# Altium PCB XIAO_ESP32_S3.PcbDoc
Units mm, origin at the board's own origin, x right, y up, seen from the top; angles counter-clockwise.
Board outline 54 x 39 mm, 2 copper layers (Top Layer, Bottom Layer), stack 1.671 mm thick; 8 components, 14 nets, 41 pads, 0 vias.
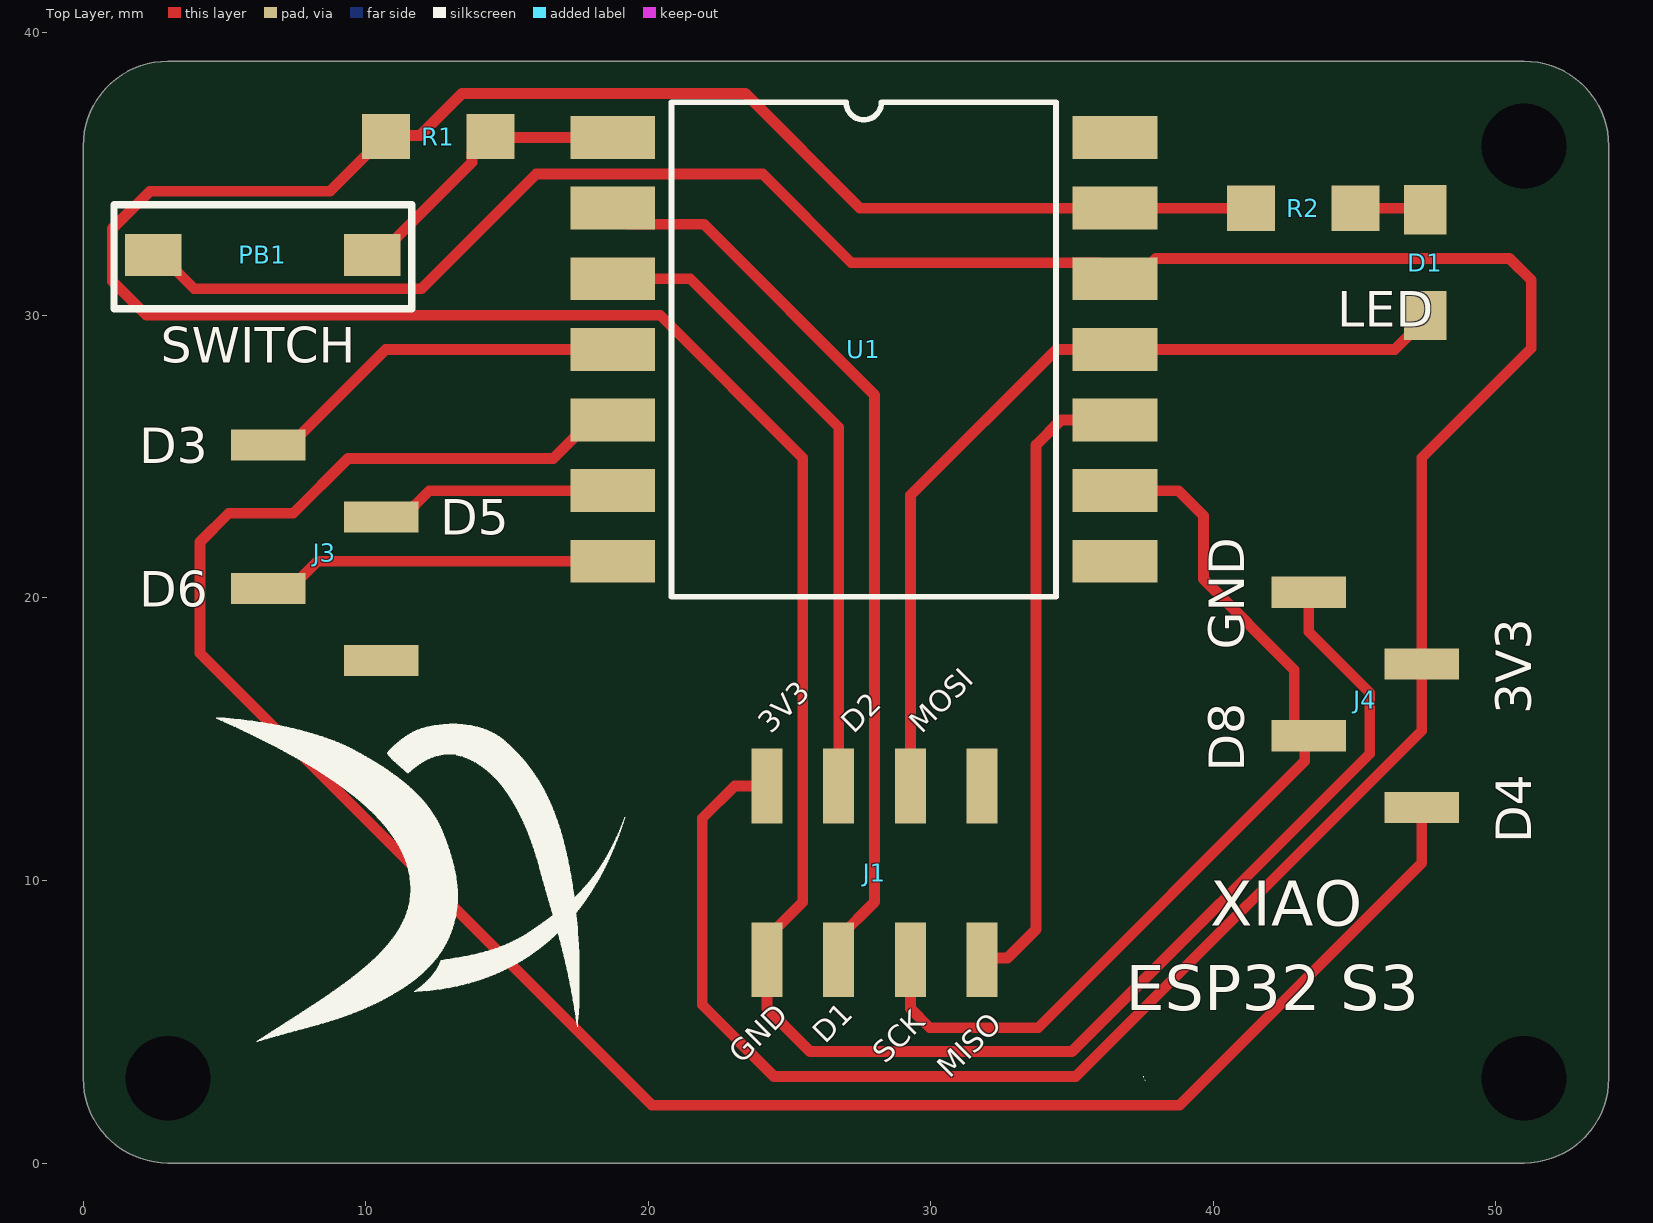
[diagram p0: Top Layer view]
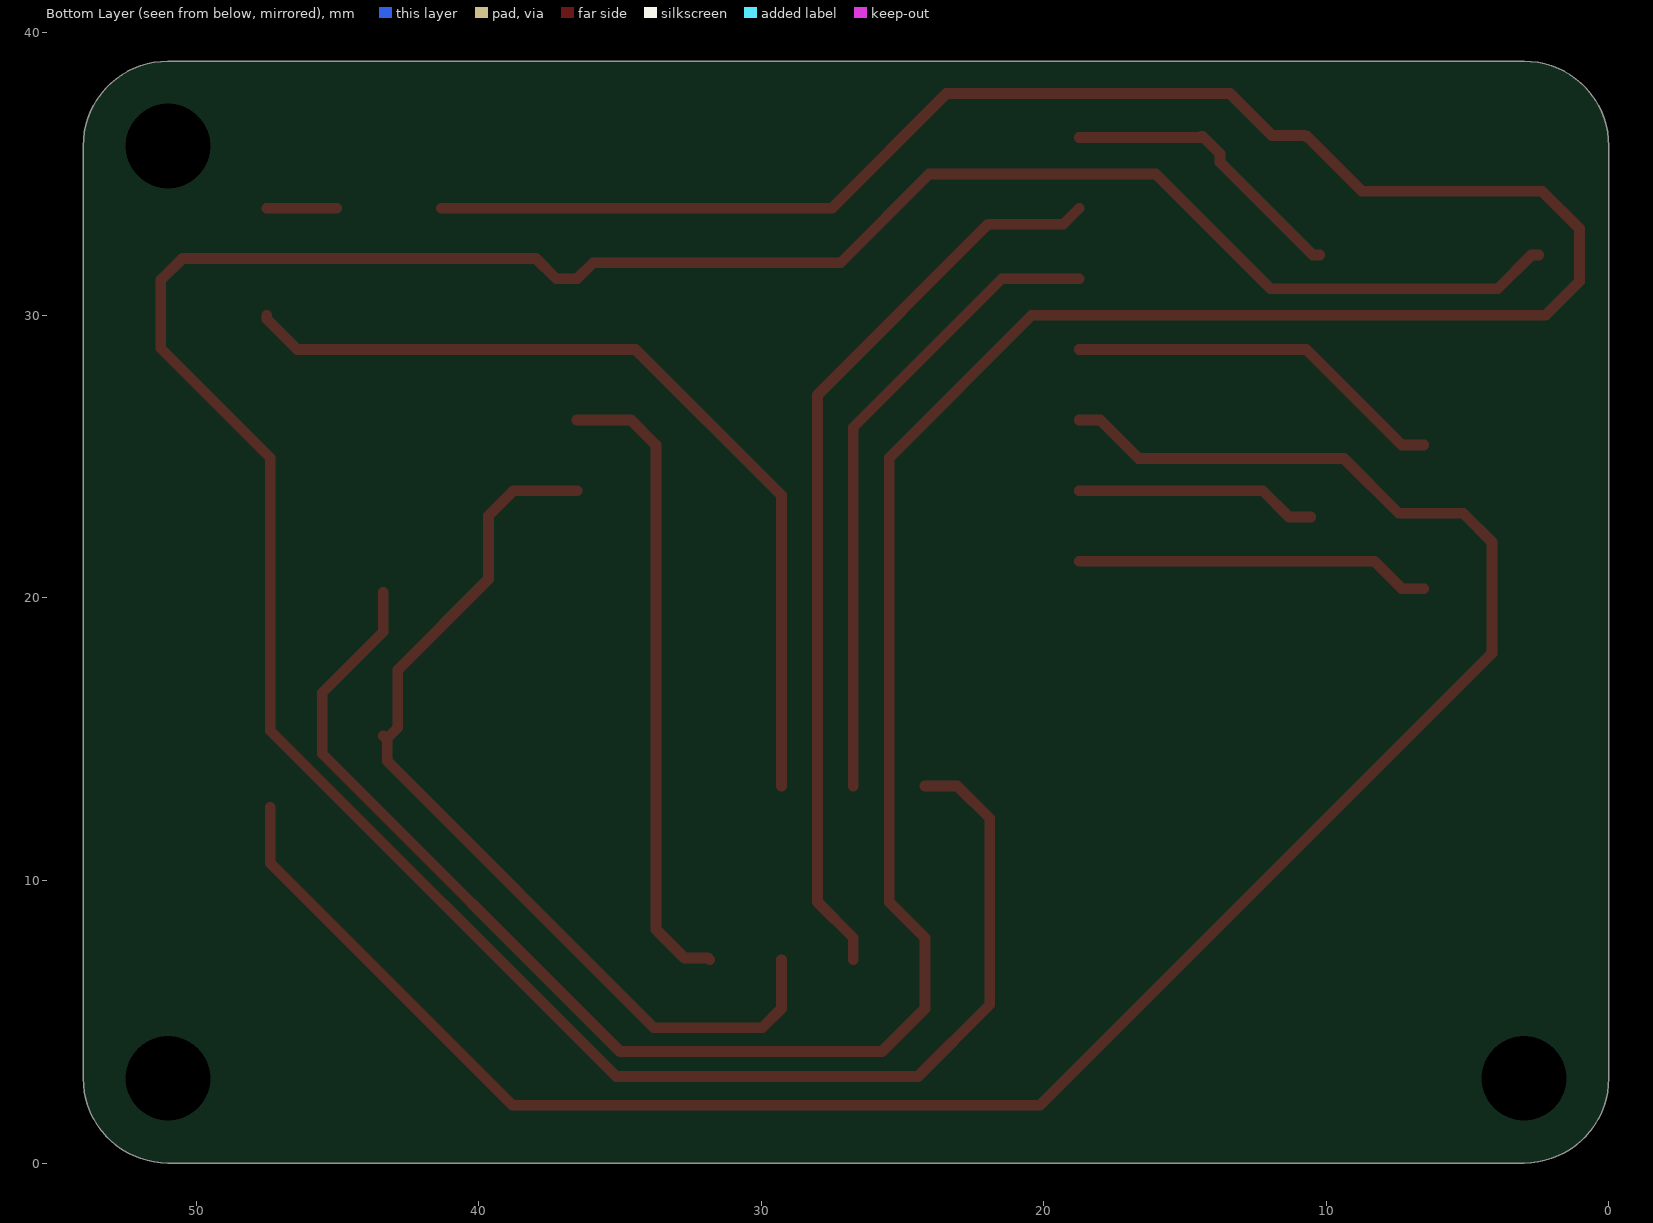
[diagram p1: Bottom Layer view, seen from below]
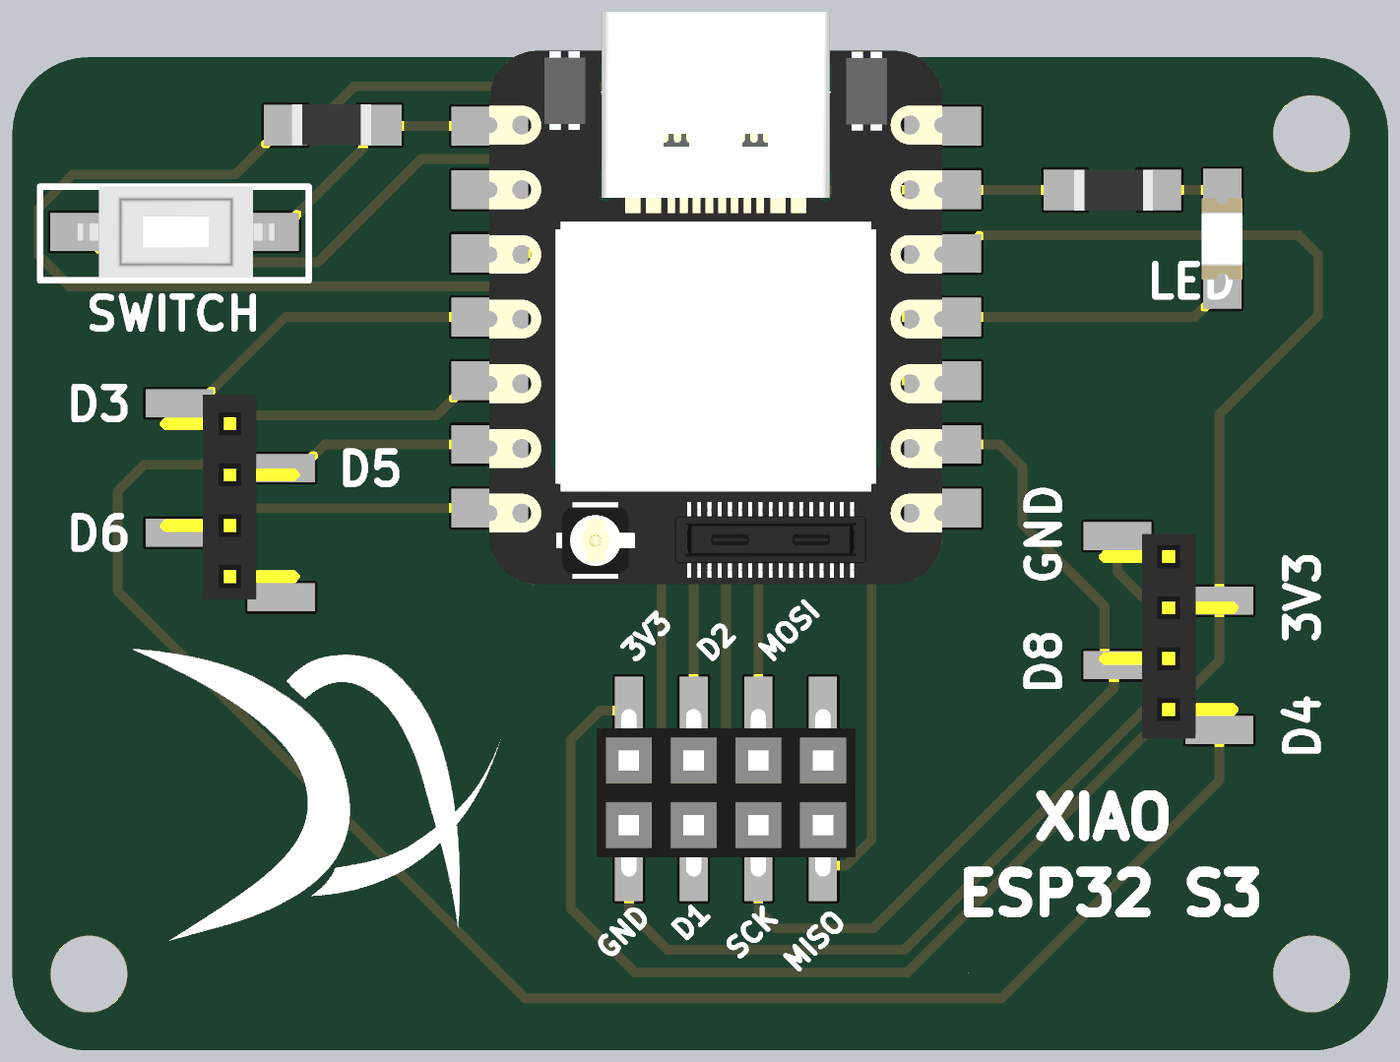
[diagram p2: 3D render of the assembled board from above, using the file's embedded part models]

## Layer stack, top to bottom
Top Solder: solder mask 0.0102, Solder Resist, Dk 3.5
Top Layer: signal copper 0.0356
Dielectric 1: dielectric 1.6, FR-4, Dk 4.8
Bottom Layer: signal copper 0.0356
Bottom Solder: solder mask 0.0102, Solder Resist, Dk 3.5

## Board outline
3,0 cw(c3,3) 0,3 0,36 cw(c3,36) 3,39 51,39 cw(c51,36) 54,36 54,3 cw(c51,3) 51,0

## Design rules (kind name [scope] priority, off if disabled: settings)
Clearance [All] p1: gap=0.254 ignorepadtopadclearanceinfootprint=FALSE
PolygonConnect [All] p1: connectstyle=Relief reliefconductorwidth=0.254 reliefentries=4 polygonreliefangle="90 Angle" airgapwidth=0.254
RoutingVias [All] p1: holewidth=0.711 width=1.27 viastyle="Through Hole" minholewidth=0.711 minwidth=1.27 maxholewidth=0.711 maxwidth=1.27
SolderMaskExpansion [All] p1: expansion=0.102 istentingtop=FALSE
SupplyNets "Schematic Supply Nets_2" [InNet('5V')] p1: voltage=0.000
SupplyNets "Schematic Supply Nets_1" [InNet('3V3')] p2: voltage=0.000
SupplyNets "Schematic Supply Nets" [InNet('GND')] p3: voltage=0.000
Width [All] p1: maxlimit=0.762 minlimit=0.254 preferedwidth=0.381 minimp=50.000000 maximp=50.000000 favimp=50.000000
30 further rules are at their usual default settings.

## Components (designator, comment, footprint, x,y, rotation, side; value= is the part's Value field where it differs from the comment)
D1 "Led" LED1206 47.5,33.75 r270 top
J1 "Header 4x2" HDR4X2_FEMALE 24.201,7.196 r90 top
J3 "Header 1x4" HDR4X1_FEMALE 6.548,25.411 r0 top
J4 "Header 1x4" HDR4X1_FEMALE 47.378,12.584 r180 top
PB1 "Push_button" "6x3x2.5mm SMD" 10.231,32.142 r180 top
R1 "R10K" RES1206 10.722,36.333 r0 top
R2 "R499" RES1206 45.029,33.793 r180 top
U1 "XIAO ESP32 S3" XIAO_ESP32_S3 18.74,36.3 r0 top

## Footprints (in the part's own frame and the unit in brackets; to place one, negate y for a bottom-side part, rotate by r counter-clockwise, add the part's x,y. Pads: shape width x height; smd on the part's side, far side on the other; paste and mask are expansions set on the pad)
"6x3x2.5mm SMD" [mm]
  rect 2x1.5 smd: 1(0,0) 2(7.75,0)
  silkscreen extent -1.4,-1.78 9.14,1.91, body extent -0.08,-1.79 7.7,1.79, height 2.54
HDR4X1_FEMALE [mm]
  rect 2.65x1.1 smd: 1(0,0) 2(4,-2.54) 3(0,-5.08) 4(4,-7.62)
  body extent -0.76,-7.7 4.74,0.34, height 2.33
HDR4X2_FEMALE [mm]
  rect 2.65x1.1 smd: 1(0,0) 2(0,-2.54) 3(0,-5.08) 4(0,-7.62) 5(6.15,-7.62) 6(6.15,-5.08) 7(6.15,-2.54) 8(6.15,0)
  body extent -0.37,-8.89 6.21,1.27, height 7.5
LED1206 [mm]
  rect 1.75x1.5 smd: 1(0,0) 2(3.75,0)
  body extent 0.28,-0.81 3.48,0.79, height 1.1
RES1206 [mm]
  rect 1.7x1.6 smd: 1(0,0) 2(3.7,0)
  body extent 0.25,-0.79 3.35,0.81, height 0.55
XIAO_ESP32_S3 [mm]
  rect 3x1.52 smd: 1(0,0) 2(0,-2.5) 3(0,-5) 4(0,-7.5) 5(0,-10) 6(0,-12.5) 7(0,-15) 8(17.78,-15) 9(17.78,-12.5) 10(17.78,-10) 11(17.78,-7.5) 12(17.78,-5) 13(17.78,-2.5) 14(17.78,0)
  silkscreen extent 2.08,-16.25 15.7,1.25, body extent -0.02,-18 17.76,4.49, height 4.47

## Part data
D1: "1206"
PB1: "PTS636SM25FSMTR LFS"

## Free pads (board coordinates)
  round 1.524 hole 3: 2(3,3) 2(51,3) 2(51,36)

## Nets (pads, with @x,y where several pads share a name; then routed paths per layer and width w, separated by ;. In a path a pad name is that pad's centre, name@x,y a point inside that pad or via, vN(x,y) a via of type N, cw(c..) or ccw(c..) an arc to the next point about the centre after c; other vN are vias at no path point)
3V3: J1.8 J4.3 PB1.2 U1.12 | length 111.6
  Top Layer w0.381: PB1.2 2.731,32.142 3.926,30.947 11.977,30.947 16.034,35.005 24.055,35.005 27.19,31.87 35.95,31.87 U1.12 37.26,31.3 37.975,32.015 50.49,32.015 51.252,31.253 51.252,28.84 47.378,24.966 J4.3 47.378,15.305 35.132,3.059 24.455,3.059 21.915,5.599 21.915,12.203 23.058,13.346 J1.8
5V: U1.14
D0/A0: PB1.1 R1.2 U1.1 | length 10.4
  Top Layer w0.381: PB1.1 10.481,32.142 13.762,35.424 13.762,35.723 14.372,36.333 R1.2 14.455,36.3 U1.1
D1/A1: J1.2 U1.2 | length 32.5
  Top Layer w0.381: U1.2 19.31,33.23 21.97,33.23 28.011,27.189 28.011,9.241 26.741,7.971 J1.2
D2/A2: J1.7 U1.3 | length 22.9
  Top Layer w0.381: U1.3 21.487,31.3 26.741,26.046 J1.7
D3/A3: J3.1 U1.4 | length 13.6
  Top Layer w0.381: J3.1 7.323,25.411 10.712,28.8 U1.4
D4/SDA: J4.1 U1.5 | length 75.7
  Top Layer w0.381: U1.5 18,26.3 16.636,24.936 9.375,24.936 7.437,22.998 5.151,22.998 4.135,21.982 4.135,18.045 20.137,2.043 38.806,2.043 47.378,10.615 J4.1
D5/A5: J3.2 U1.6 | length 9.3
  Top Layer w0.381: J3.2 11.323,22.871 12.252,23.8 U1.6 U1.6@18,23.8
D6/TX: J3.3 U1.7 | length 12.6
  Top Layer w0.381: J3.3 7.323,20.331 8.292,21.3 U1.7
D8/SCK: J1.3 J4.2 U1.9 | length 33.6
  Top Layer w0.381: J1.3 29.281,5.472 29.962,4.791 33.807,4.791 43.242,14.226 43.242,14.988 J4.2 ; U1.9 38.766,23.8 39.652,22.915 39.652,20.669 42.87,17.45 42.87,15.405 J4.2@43.151,15.124
D9/A9: J1.4 U1.10 | length 22.7
  Top Layer w0.381: J1.4 31.884,7.259 32.719,7.259 33.726,8.266 33.726,25.411 34.615,26.3 U1.10
D10/A10: D1.2 J1.6 U1.11 | length 31.2
  Top Layer w0.381: J1.6 29.281,23.633 34.448,28.8 U1.11 46.425,28.8 47.5,29.875 D1.2
GND: J1.1 J4.4 R1.1 R2.2 U1.13 | length 125.8
  Top Layer w0.381: R2.2 36.527,33.793 U1.13 27.496,33.8 23.439,37.857 13.406,37.857 11.92,36.371 10.76,36.371 R1.1 10.672,36.333 8.739,34.4 2.36,34.4 1.037,33.076 1.037,31.208 2.24,30.005 20.424,30.005 25.471,24.958 25.471,9.241 24.201,7.971 24.201,5.472 25.725,3.948 34.996,3.948 45.537,14.489 45.537,16.648 43.378,18.807 J4.4
NetD1_1: D1.1 R2.1 | length 2.5
  Top Layer w0.381: R2.1 D1.1@47.5,33.793
pads on no net: J1.5 J3.4 U1.8

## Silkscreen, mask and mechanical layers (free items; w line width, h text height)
Top Overlay:
  drawing of 9 lines, arcs and shapes, not listed
  text "LED" at 44.394,29.602 h1.27
  text "SWITCH" at 2.738,28.332 h1.27
  text "D3" at 1.976,24.776 h1.27
  text "D5" at 12.644,22.236 h1.27
  text "D6" at 1.976,19.696 h1.27
  text "GND" at 41.092,18.172 h1.27 r90
  text "3V3" at 51.252,15.886 h1.27 r90
  text "3V3" at 24.328,15.157 h0.76 r45
  text "D2" at 27.274,15.157 h0.76 r45
  text "MOSI" at 29.682,15.157 h0.76 r45
  text "D8" at 41.092,13.854 h1.27 r90
  text "D4" at 51.252,11.314 h1.27 r90
  text "XIAO" at 39.9,8.4 h1.6
  text "ESP32 S3" at 36.9,5.4 h1.6
  text "D1" at 26.274,4.192 h0.76 r45
  text "GND" at 23.312,3.473 h0.76 r45
  text "SCK" at 28.392,3.473 h0.76 r45
  text "MISO" at 30.678,2.965 h0.76 r45
Mechanical 1:
  the board outline again, w0.254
